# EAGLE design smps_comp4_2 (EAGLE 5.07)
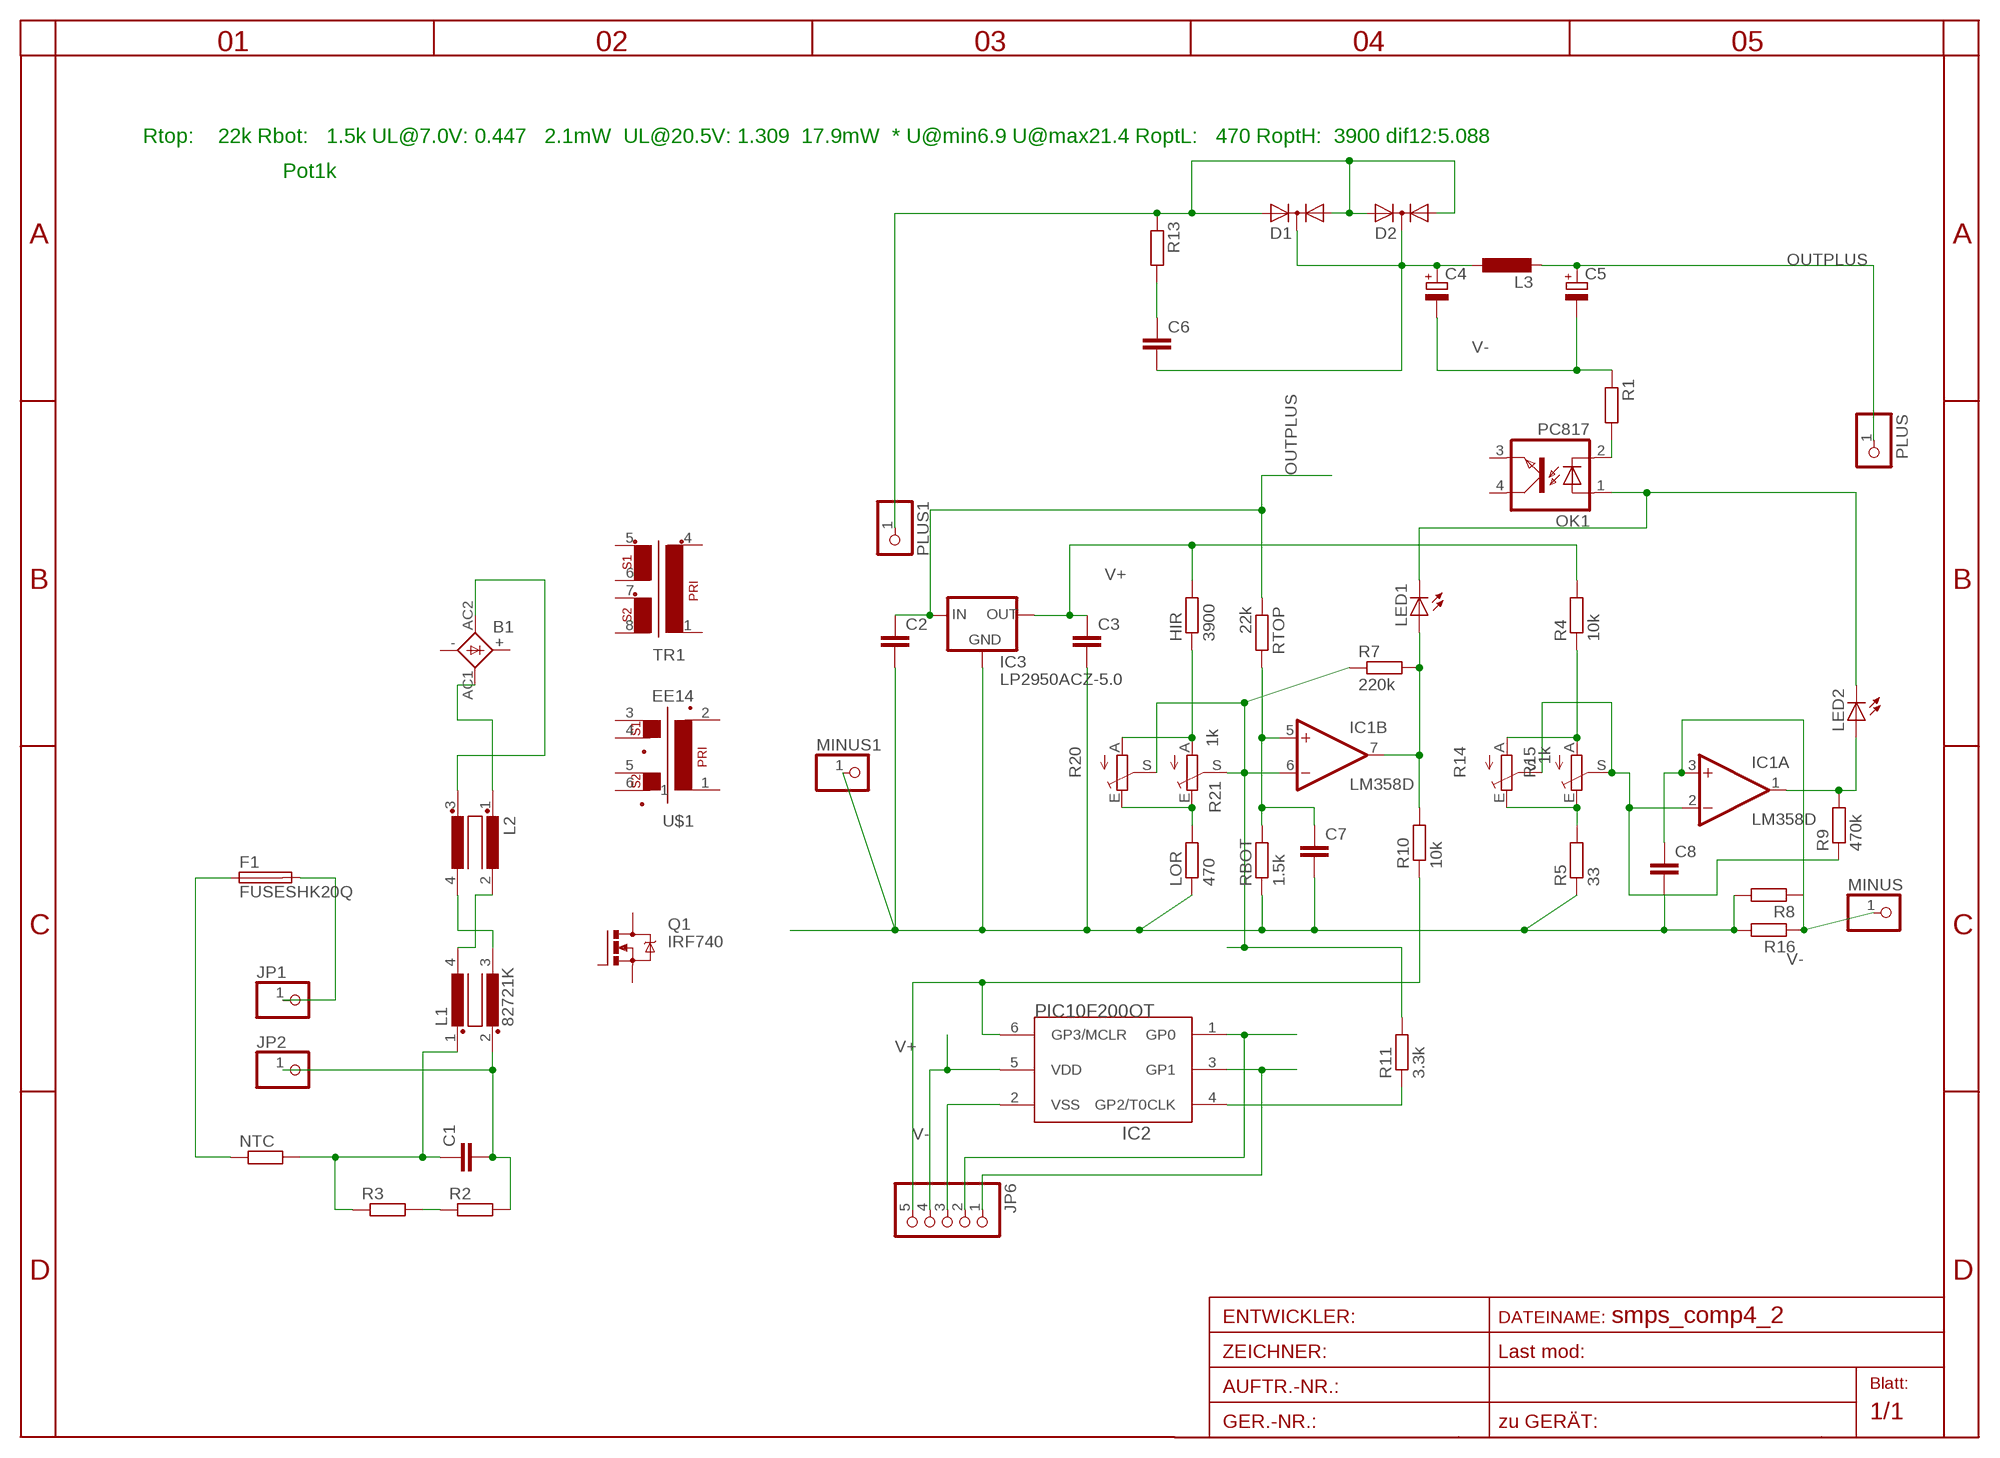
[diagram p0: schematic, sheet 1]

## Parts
B1  KBL  [KBL]
C1  C-EU150-084X183  [C150-084X183]
C2  C-EUC1206  [C1206]
C3  C-EUC1206  [C1206]
C4  CPOL-EUE5-8.5  [E5-8,5]
C5  CPOL-EUE5-8.5  [E5-8,5]
C6  C-EUC0805  [C0805]
C7  C-EUC0805  [C0805]
C8  C-EUC0805  [C0805]
D1  DIODE-2AC|CAIW220V  [IW220ABS]
D2  DIODE-2AC|CAIW220V  [IW220ABS]
F1  FUSESHK20Q  [SHK20Q]
HIR  3900  R-EU_R0805  [R0805]
IC1  LM358D  [SO08]
IC2  PIC10F200OT  [SOT23-6]
IC3  LP2950ACZ-5.0  [TO92]
JP1  PINHD-1X12MM2  [1X2MM2]
JP2  PINHD-1X12MM2  [1X2MM2]
JP6  PINHD-1X5/90  [1X05/90]
L1  82721K  [82721K]
L2  R1405VB1  [B1]
L3  L-EU0207/12  [0207/12]
LED1  LED3MM  [LED3MM]
LED2  LED3MM  [LED3MM]
LOR  470  R-EU_R0805  [R0805]
MINUS  PINHD-1X12MM2  [1X2MM2]
MINUS1  PINHD-1X11X0.4  [1X01]
NTC  R-EU_0204/7  [0204/7]
OK1  PC817  [DIL04]
PLUS  PINHD-1X12MM2  [1X2MM2]
PLUS1  PINHD-1X11X0.4  [1X01]
Q1  IRF740  [TO220BV]
R1  R-EU_R0805  [R0805]
R2  R-EU_R1206  [R1206]
R3  R-EU_R1206  [R1206]
R4  10k  R-EU_R0805  [R0805]
R5  33  R-EU_R0805  [R0805]
R7  220k  R-EU_R0805  [R0805]
R8  R-EU_R2010  [R2010]
R9  470k  R-EU_R0805  [R0805]
R10  10k  R-EU_0207/15  [0207/15]
R11  3.3k  R-EU_0207/15  [0207/15]
R13  R-EU_R0805  [R0805]
R14  TRIM_EU-S64W  [S64W]
R15  1k  TRIM_EU-CA6V  [CA6V]
R16  R-EU_R2010  [R2010]
R20  TRIM_EU-S64W  [S64W]
R21  1k  TRIM_EU-CA6V  [CA6V]
RBOT  1.5k  R-EU_R0805  [R0805]
RTOP  22k  R-EU_R0805  [R0805]
TR1  EE20-2  [EE20-2]
U$1  EE14  [EE14]

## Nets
A: R4.1 R14.A R15.A
A1: HIR.1 R20.A R21.A
CPLUS: C4.+ C6.2 D1.C D2.C L3.1
E: R5.2 R14.E R15.E
E1: LOR.2 R20.E R21.E
N$1: C1.2 JP2.1 L1.2 R2.2
N$2: C1.1 L1.1 NTC.2 R3.1
N$3: F1.2A JP1.1
N$5: L1.4 L2.2
N$6: R2.1 R3.2
N$7: B1.AC2(AC1) L2.3
N$8: B1.AC1(AC2) L2.1
N$9: F1.1A NTC.1
N$10: IC1.6(B:-IN) R7.1 R11.2 R20.S R21.S
N$11: IC1.1(A:OUT) LED2.A R9.2
N$12: OK1.2(C) R1.2
N$13: LED1.K(C) LED2.K(C) OK1.1(A)
N$14: L1.3 L2.4
N$15: IC2.6(GP3/MCLR) JP6.5 R10.1
N$16: C7.1 IC1.5(B:+IN) RBOT.2 RTOP.2
N$17: IC2.1(GP0) JP6.2
N$18: IC2.3(GP1) JP6.1
N$19: IC2.4(GP2/T0CLK) R11.1
N$27: C6.1 R13.2
OUT: C8.1 IC1.3(A:+IN) MINUS.1 R8.1 R16.1
OUTB: IC1.7(B:OUT) LED1.A R7.2 R10.2
OUTPLUS: C2.1 C5.+ IC3.3(IN) L3.2 PLUS.1 RTOP.1
S: IC1.2(A:-IN) R9.1 R14.S R15.S
TPLUS: D1.A1 D1.A2 D2.A1 D2.A2 PLUS1.1 R13.1
V+: C3.1 HIR.2 IC2.5(VDD) IC3.1(OUT) JP6.4 R4.2
V-: C2.2 C3.2 C4.- C5.- C7.2 C8.2 IC2.2(VSS) IC3.2(GND) JP6.3 LOR.1 MINUS1.1 R1.1 R5.1 R8.2 R16.2 RBOT.1
Unconnected: B1.+ B1.- OK1.3(EMIT) OK1.4(COL) Q1.D Q1.G Q1.S TR1.1 TR1.4 TR1.5 TR1.6 TR1.7 TR1.8 U$1.1 U$1.2 U$1.3 U$1.4 U$1.5 U$1.6

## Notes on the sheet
- Rtop:    22k Rbot:   1.5k UL@7.0V: 0.447   2.1mW  UL@20.5V: 1.309  17.9mW  * U@min6.9 U@max21.4 RoptL:   470 RoptH:  3900 dif12:5.088
- Pot1k

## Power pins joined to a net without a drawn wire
V+: IC1.8(P:V+)
V-: IC1.4(P:V-)

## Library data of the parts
B1 = rectifier:KBL: DIOTEC RECTIFIER
C1-C3 C6-C8 = rcl:C-EU: CAPACITOR, European symbol
C4 C5 = rcl:CPOL-EU: POLARIZED CAPACITOR, European symbol
D1 D2 = diode:DIODE-2AC|CA: Dual DIODE Anode-Cathode|Cathode-Anode
F1 = fuse:FUSE: Fuse
HIR LOR NTC R1-R5 R7-R11 R13 R16 RBOT RTOP = rcl:R-EU_: RESISTOR, European symbol
IC1 = linear:LM358: OP AMP also LM158; LM258; LM2904 Source: http://cache.national.com/ds/LM/LM158.pdf
IC2 = microchip-5:PIC10F20*: uPC nW 0,25/0,5k Program Flash memory
IC3 = v-reg:LP2950?*: Source: http://cache.national.com/ds/LP/LP2950.pdf
JP1 JP2 MINUS MINUS1 PLUS PLUS1 = pinhead:PINHD-1X1: PIN HEADER
JP6 = pinhead:PINHD-1X5: PIN HEADER
L1 = inductors:82721K: FILTER
L2 = inductor-nkl:R1405V: Übertrager (verlustarm) bis typ. 400kHz Power transformer (low loss) up to typ. 400kHz
L3 = rcl:L-EU: INDUCTOR, European symbol
LED1 LED2 = led:LED: LED
OK1 = optocoupler:PC817: SHARP OPTO COUPLER
Q1 = transistor-power:IRF740: N-CHANNEL MOS FET
R14 R15 R20 R21 = pot:TRIM_EU-: POTENTIOMETER
TR1 = trafo:EE20-2: TRANSFORMER 1 primary winding, 2 secondary windings ERA
U$1 = trafo:EE14

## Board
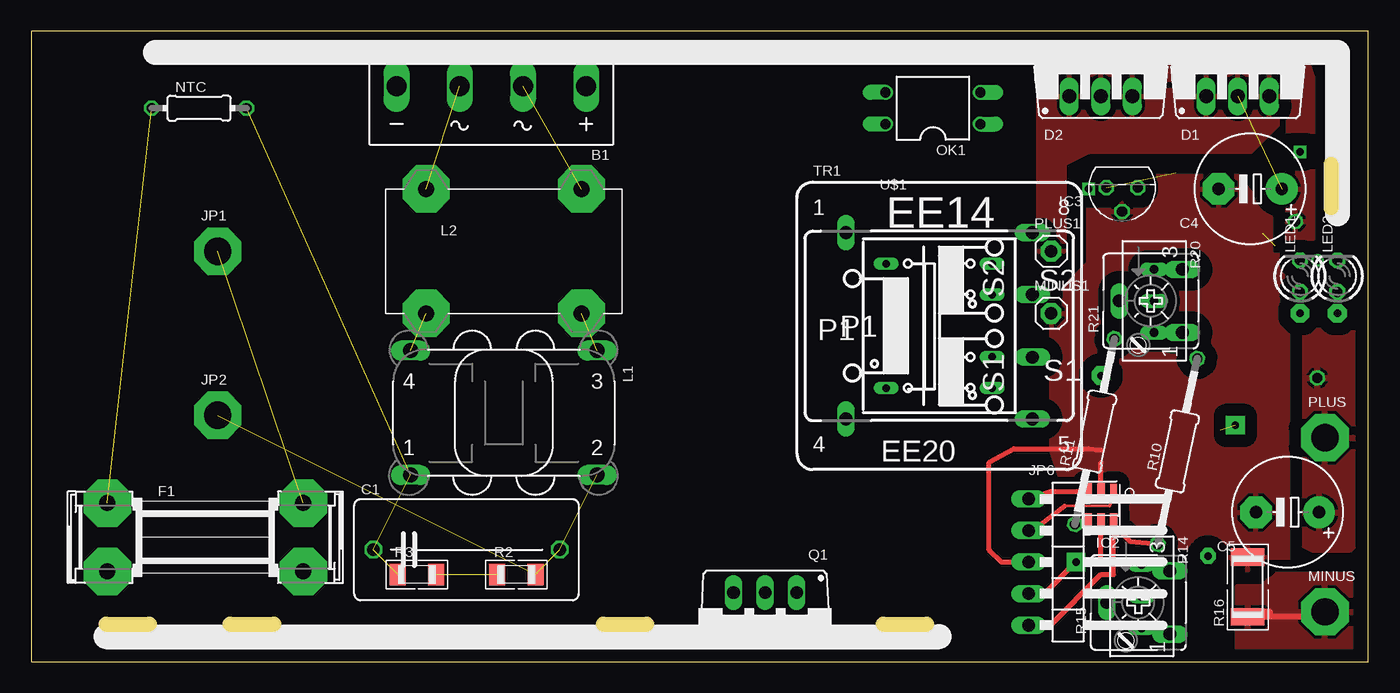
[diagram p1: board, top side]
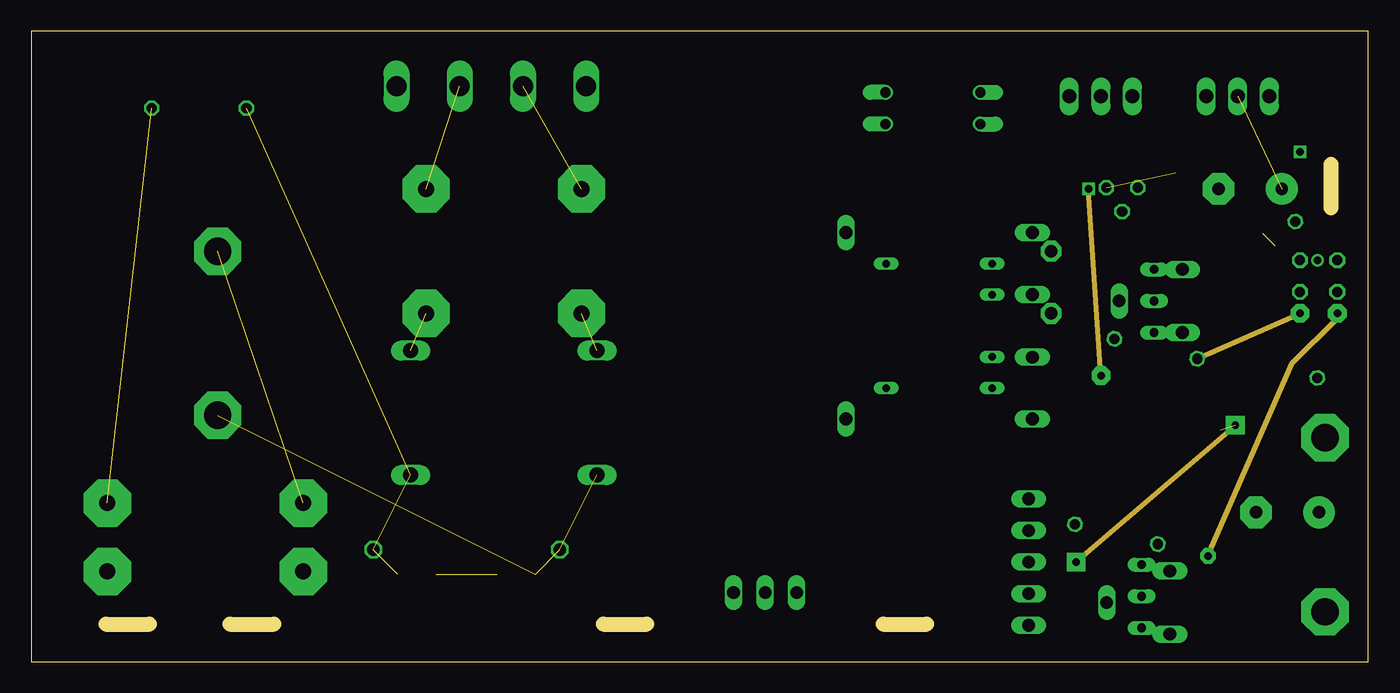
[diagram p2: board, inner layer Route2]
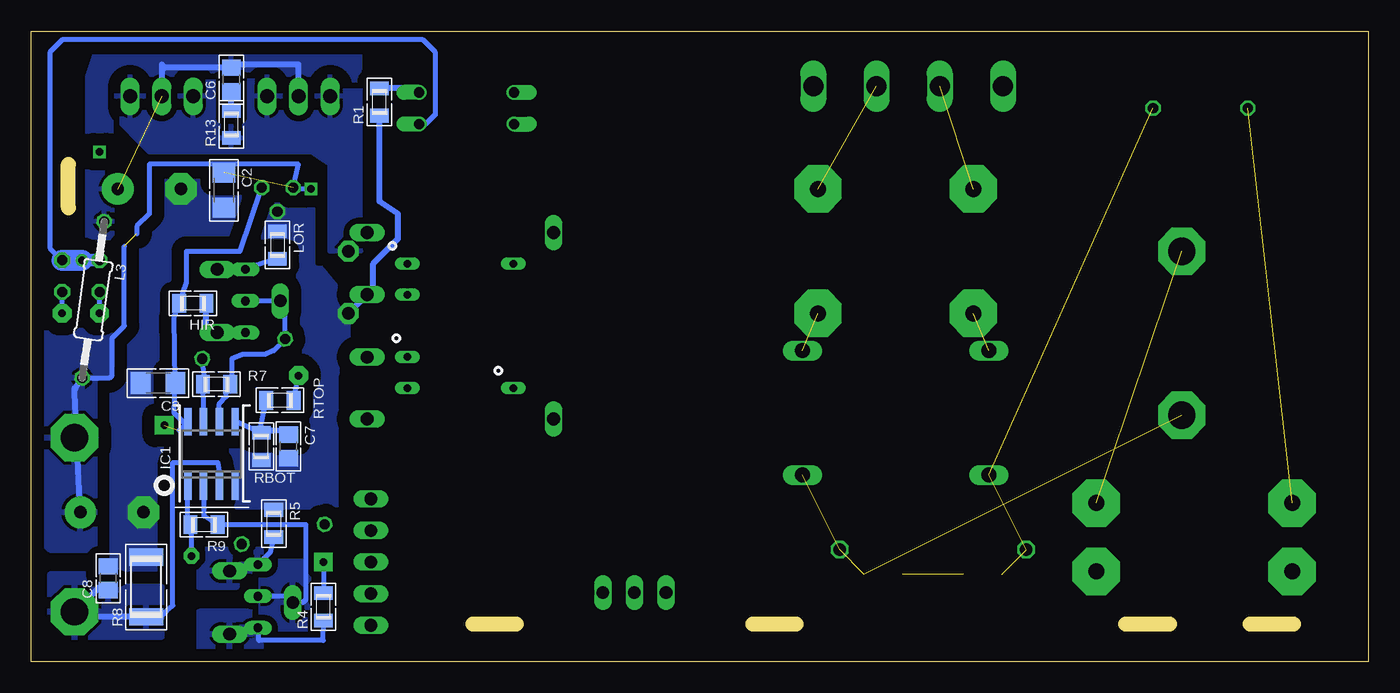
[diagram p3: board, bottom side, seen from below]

Size 107.5 x 50.7 mm. Coordinates in mm from the lower left corner, seen from the top.
Outline: 0,0 107.5,0 107.5,50.7 0,50.7 0,0
Copper layers (1*16): Top 0.035mm / dielectric 1.5mm / Bottom 0.035mm
Design rules "default *": minimum track width 10mil, minimum drill 20mil, track to track 8mil, track to pad 8mil, pad to pad 8mil, via to via 8mil, smd to smd 8mil, copper to edge 40mil, drill to drill 8mil, minimum pad ring 8mil, minimum via ring 8mil, stop-mask expansion 4mil, vias tented up to drill 0mil, thermal gap 10mil
Milling: 5 lines

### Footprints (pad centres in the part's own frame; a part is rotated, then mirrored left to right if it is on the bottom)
KBL = drill 1.6 long: + -7.62,-1.27; - 7.62,-1.27; AC1 2.54,-1.27; AC2 -2.54,-1.27
C150-084X183 = drill 1.016 octagon: 1 -7.493,0; 2 7.493,0
C1206 = smd 1.6 x 1.8: 1 -1.4,0; 2 1.4,0
E5-8,5 = drill 1 pad 2.54 round: + -2.54,0 | drill 1 pad 2.54 octagon: - 2.54,0
C0805 = smd 1.3 x 1.5: 1 -0.95,0; 2 0.95,0
IW220ABS = drill 1.118 long: A1 -2.54,-2.54; A2 2.54,-2.54; C 0,-2.54
SHK20Q = drill 1.3 pad 3.81 octagon: 1A -7.874,2.75; 1B -7.874,-2.75; 2A 7.874,2.75; 2B 7.874,-2.75
R0805 = smd 1.1 x 1.5: 1 -1.1,0; 2 1.1,0
SO08 = smd 0.6 x 2.2: 1 -1.905,-2.6; 2 -0.635,-2.6; 3 0.635,-2.6; 4 1.905,-2.6; 5 1.905,2.6; 6 0.635,2.6; 7 -0.635,2.6; 8 -1.905,2.6
SOT23-6 = smd 0.55 x 1.2: 1 -1.016,-1.2 | smd 0.6 x 1.27: 2 0,-1.2; 3 1.016,-1.2; 4 1.016,1.2; 5 0,1.2; 6 -1.016,1.2
TO92 = drill 0.813 octagon: 1 -1.27,0; 2 0,1.905; 3 1.27,0
1X2MM2 = drill 2.2 pad 3.81 octagon: 1 0,0
1X05/90 = drill 1.016 long: 1 -5.08,-3.81; 2 -2.54,-3.81; 3 0,-3.81; 4 2.54,-3.81; 5 5.08,-3.81
82721K = drill 1.194 long: 1 7.493,5.004; 2 -7.493,5.004; 3 -7.493,-5.004; 4 7.493,-5.004
B1 = drill 1.27 pad 3.81 octagon: 1 -6.25,5; 2 -6.25,-5; 3 6.25,5; 4 6.25,-5
0207/12 = drill 0.813 octagon: 1 -6.35,0; 2 6.35,0
LED3MM = drill 0.8 pad 1.27 octagon: A -1.27,0; K 1.27,0
1X01 = drill 1 pad 1.676 octagon: 1 0,0
0204/7 = drill 0.813 octagon: 1 -3.81,0; 2 3.81,0
DIL04 = drill 0.813 offset: 1 -1.27,-3.81; 2 1.27,-3.81; 3 1.27,3.81; 4 -1.27,3.81
TO220BV = drill 1.016 long: D 0,-2.54; G -2.54,-2.54; S 2.54,-2.54
R1206 = smd 1.3 x 1.7: 1 -1.55,0; 2 1.55,0
R2010 = smd 1.4 x 2.7: 1 -2.4,0; 2 2.4,0
0207/15 = drill 0.813 octagon: 1 -7.62,0; 2 7.62,0
S64W = drill 0.7 long: A 2.54,1.27; E -2.54,1.27; S 0,1.27
CA6V = drill 1.016 long: A -2.54,-2.54; E 2.54,-2.54; S 0,2.54
EE20-2 = drill 1.016 long: 1 -7.493,7.493; 4 -7.493,-7.493; 5 7.493,-7.493; 6 7.493,-2.515; 7 7.493,2.515; 8 7.493,7.493
EE14 = drill 0.6 pad 1 long: 1 4.25,-5; 2 4.25,5; 3 -4.25,5 | drill 0.6 pad 1.016 long: 4 -4.25,2.5; 5 -4.25,-2.5; 6 -4.25,-5

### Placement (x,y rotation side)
B1  37,45 180 top
C1  35,9 0 top
C2  92,37.9 270 bottom
C3  97.3,22.4 180 bottom
C4  98,38 180 top
C5  101,12 180 top
C6  91.4,46.8 90 bottom
C7  86.8,17.3 270 bottom
C8  101.3,6.7 90 bottom
D1  97,48 0 top
D2  86,48 0 top
F1  14,10 0 top
HIR  94.5,28.8 180 bottom
IC1  93,16.7 0 bottom
IC2  86,12.5 180 top
IC3  87.7,38.1 180 top
JP1  15,33 0 top
JP2  15,19.8 0 top
JP6  84,8 270 top
L1  38,20 180 top
L2  38,33 0 top
L3  102.5,29.1 262 bottom
LED1  102,31 90 top
LED2  105,31 90 top
LOR  87.7,33.5 270 bottom
MINUS  104,4 0 top
MINUS1  82,28 0 top
NTC  13.5,44.5 0 top
OK1  72.5,44.5 90 top
PLUS  104,18 0 top
PLUS1  82,33 0 top
Q1  59,3 180 top
R1  79.5,45 90 bottom
R2  39,7 0 top
R3  31,7 0 top
R4  84,4.4 90 bottom
R5  88,11.1 270 bottom
R7  92.6,22.3 180 bottom
R8  98.25,6 90 bottom
R9  93.6,11 180 bottom
R10  92.15,16.9 78 top
R11  85.5,18.5 78 top
R13  91.4,43.2 90 bottom
R14  88,5.25 270 top
R15  89,4.75 90 top
R16  97.8,6 90 top
R20  89,29 270 top
R21  90,29 90 top
RBOT  89,17.3 90 bottom
RTOP  87.5,21 180 bottom
TR1  73,27 0 top
U$1  73,27 180 top

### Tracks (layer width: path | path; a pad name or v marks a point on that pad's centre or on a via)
A
  Bottom 0.4: R4.1 84.01,1.7 89.2,1.7 89.2,2.71 R14.A
  Bottom 0.5: R14.A R15.A
  pour Bottom (isolate 0.5, rank 2): 89,4 94,4 94,1 89,1
A1
  Bottom 0.5: R20.A R21.A 93.46,26.46 HIR.1
CPLUS  (1 unrouted)
  Bottom 0.5: D2.C 86,48 91.15,48 C6.2 96.75,47.75 97,48 D1.C
  pour Bottom (isolate 1): 81,50 102,50 103,47 103,34 101,34 101,37 101.1,46.8 81.1,46.8
  pour Top (isolate 1): 81,50 102,50 103,47 103,34 101,34 101,37 101.1,46.8 81.1,46.8
E
  Bottom 0.406: R5.2 88.27,8.8 R14.E R15.E
  pour Bottom (isolate 0.5, rank 2): 90,7 89,7 89,9 94,9 94,6 91,6
E1
  Bottom 0.406: LOR.2 90.27,31.6 R20.E
  Bottom 0.5: R20.E R21.E
N$1  (3 unrouted)
N$2  (3 unrouted)
N$3  (1 unrouted)
N$4  (via drill 0.6)
  other vias: 102,41
N$5  (1 unrouted)
N$6  (1 unrouted)
N$7  (1 unrouted)
N$8  (1 unrouted)
N$9  (1 unrouted)
N$10
  Bottom 0.4: 91.36,24.34 90.5,24.7 88.7,24.7
  Bottom 0.406: R20.S R21.S 87.08,29 R11.2 87.08,25.92 88,25 88.7,24.7 | IC1.6 92.36,20.73 91.8,21.3 91.8,22 R7.1 91.36,22.43 91.36,24.34
N$11  (via drill 0.6 pad 1.25, 0.6 pad 1.5)
  Route2 0.406: v94.6,8.5 101.4,24 105,27.6 v105,28
  Bottom 0.4: v105,28 LED2.A | 94.6,10.1 R9.2 94.91,11.2 IC1.1
  Bottom 0.406: v94.6,8.5 94.6,10.1
N$12
  Bottom 0.5: R1.2 76.64,46.1 OK1.2
N$13  (via drill 0.6)
  Bottom 0.4: OK1.1 75.77,43.23 75,44 75,49 76,50 105,50 106,49 106,33.27 LED2.K
  Bottom 1: v103.4,32.27 LED1.K
  Bottom 1.676: LED2.K v103.4,32.27
N$14  (1 unrouted)
N$15
  Top 0.406: IC2.6 87.2,10.8 87.5,10.5 | JP6.5 81.92,2.92 86,7 87,7 87,10 87.5,10.5 | R10.1 88.32,9.68 87.5,10.5
N$16
  Bottom 0.4: IC1.5 RBOT.2 87.25,18.6 | C7.1 87.25,18.6 | RTOP.2 89.1,18.65 87.25,18.6
N$17
  Top 0.2: 83.1,12.5 86.7,12.5
  Top 0.254: 86.7,12.5 87,13.18
  Top 0.406: 87.2,13.2 IC2.1 87,13.18 | JP6.2 80.54,10.54 83.1,12.5
N$18
  Top 0.406: JP6.1 81.96,13.68 IC2.3
N$19
  Top 0.406: IC2.4 84.1,11.3 R11.1
N$27
  Bottom 0.5: R13.2 C6.1
OUT
  Top 0.5: R16.1 103.6,3.6 MINUS.1 | R16.1 98.8,3.6 | 98,4 99.6,4 R16.1
  Bottom 0.4: IC1.3 92.36,15.27 92.5,16 96.1,16 96.1,4.5 96.6,4.1 97,3.7 98.15,3.7 R8.1
  Bottom 0.5: C8.1 101.25,5.75 101,6 102,6 MINUS.1 103.6,3.6 R8.1
  pour Bottom (isolate 1.016, rank 3): 102,6 103,7 106,7 106,2 97,2 97,6
  pour Top (isolate 1.016, rank 3): 100,7 106,7 106,1 97,1 97,6 99,6
OUTB  (via drill 0.6 pad 1.5)
  Route2 0.406: R10.2 v102,28
  Bottom 0.4: R7.2 93.6,22.6 | v102,28 LED1.A
  Bottom 0.406: IC1.7 93.64,21.07 R7.2 | 93.6,22.6 93.6,23.04 R10.2
OUTPLUS  (via drill 0.6, 0.6 pad 1.5)  (2 unrouted)
  Route2 0.406: v86,23 v85,38
  Bottom 0.406: 99,34.4 99,35 98,36 98,40 86,40 IC3.3 86.43,38 v85,38 | L3.2 101.19,22.81 101,23 101,26 100,27 100,33.4 | RTOP.1 v86,23
  Bottom 0.5: L3.2 103.95,21.95 104,22 104,21.54 C5.+
  pour Bottom (isolate 1, rank 5): 107,28 107,10 106,9 103,9 101,10 101,28
  pour Top (isolate 1, rank 5): 107,28 107,10 106,9 103,9 101,10 101,28
S
  Bottom 0.4: IC1.2 93.6,13.4 93.6,11.7 R9.1
  Bottom 0.406: R9.1 85.4,11 85.4,5 85.65,4.75 R15.S 86.96,5.25 R14.S
  pour Bottom (isolate 0.5): 85,8 89,8 89,2 85,2
TPLUS
  pour Bottom (isolate 0.5, rank 2): 81,33 81,46 82,47 100,47 101,46 101,44 98,41 85,41 83.5,40 83.5,33
  pour Top (isolate 0.5, rank 2): 81,33 81,46 82,47 100,47 101,46 101,44 98,41 85,41 83,40 83,33
V+  (via drill 0.6 pad 1.5)  (1 unrouted)
  Top 0.406: IC2.5 86,8 v84,8 81.46,5.46 JP6.4
  Route2 0.406: v84,8 v96.8,19
  Bottom 0.4: 95,33 95,30.5 HIR.2 96,27.7 C3.1 96,20 95,19 95,18.7 IC1.8 95.6,18.6 | v84,8 R4.2
  Bottom 0.406: IC3.1 90.7,33 95,33
V-
  Top 0.406: IC2.2 86,16 | JP6.3 78,8 77,9 77,16 79,17.1 85,17.1 86,17
  Bottom 0.5: R1.1 79.5,37 78,36 78,34 80,32 80,30 MINUS1.1
  pour Bottom (isolate 1, rank 4, no thermals): 97,40 86,40 84.5,38 84.5,32 82,29 82,26 83,23 83,8 86,2 101,2 101,34
  pour Top (isolate 1, rank 4): 97,39 86,39 85,38 85,32 82,29 82,17 85,8 86,2 101,2 101,34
